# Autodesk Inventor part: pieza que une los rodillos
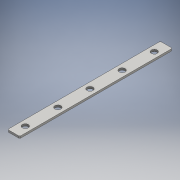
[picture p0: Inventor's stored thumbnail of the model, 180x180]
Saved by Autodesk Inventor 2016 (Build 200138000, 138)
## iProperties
Created: 2016-06
Part Number: pieza que une los rodillos
Material: Generic
Document SubType Name: Modeling
Designer: yesi alvarez
Mass: 56.7847 g
Surface Area: 270.237 cm^2
Volume: 56.7847 cm^3
Density: 1 g/cm^3
Appearance: Default
Author: yesi alvarez
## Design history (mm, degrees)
sketch "Sketch1"
  geometry: L1 (0, 0)-(30, 0); L2 (30, 0)-(30, 380); L3 (30, 380)-(0, 380); L4 (0, 380)-(0, 0); C1 r 7.5 at (15, 350); C2 r 7.5 at (15, 270); C3 r 7.5 at (15, 190); C4 r 7.5 at (15, 110); C5 r 7.5 at (15, 28.904); 5 further points
  constraints: 8 end point, 5 centre point, 4 coincident, 2 parallel, 1 horizontal, 1 perpendicular
  dimensions: "d0" = 30 distance of L3.end L2.end; "d1" = 380 distance of L2.end L1.end; "d2" = 30 distance from line of point (15, 350) L3; "d3" = 30 distance from line of L1 point (15, 30); "d4" = 80 distance of point (15, 30) point (15, 110); "d5" = 80 distance of point (15, 110) point (15, 190); "d6" = 80 distance of point (15, 190) point (15, 270); "d7" = 15 diameter of C1; "d8" = 15 diameter of C2; "d9" = 15 diameter of C3; "d10" = 15 diameter of C4; "d11" = 15 diameter of C5
extrude "Extrusion1" new body sketch "Sketch1" distance "d12" = 5; taper "d13" = 0 deg
fillet "Fillet1" dims "d14" = 3
body "Solid1"
